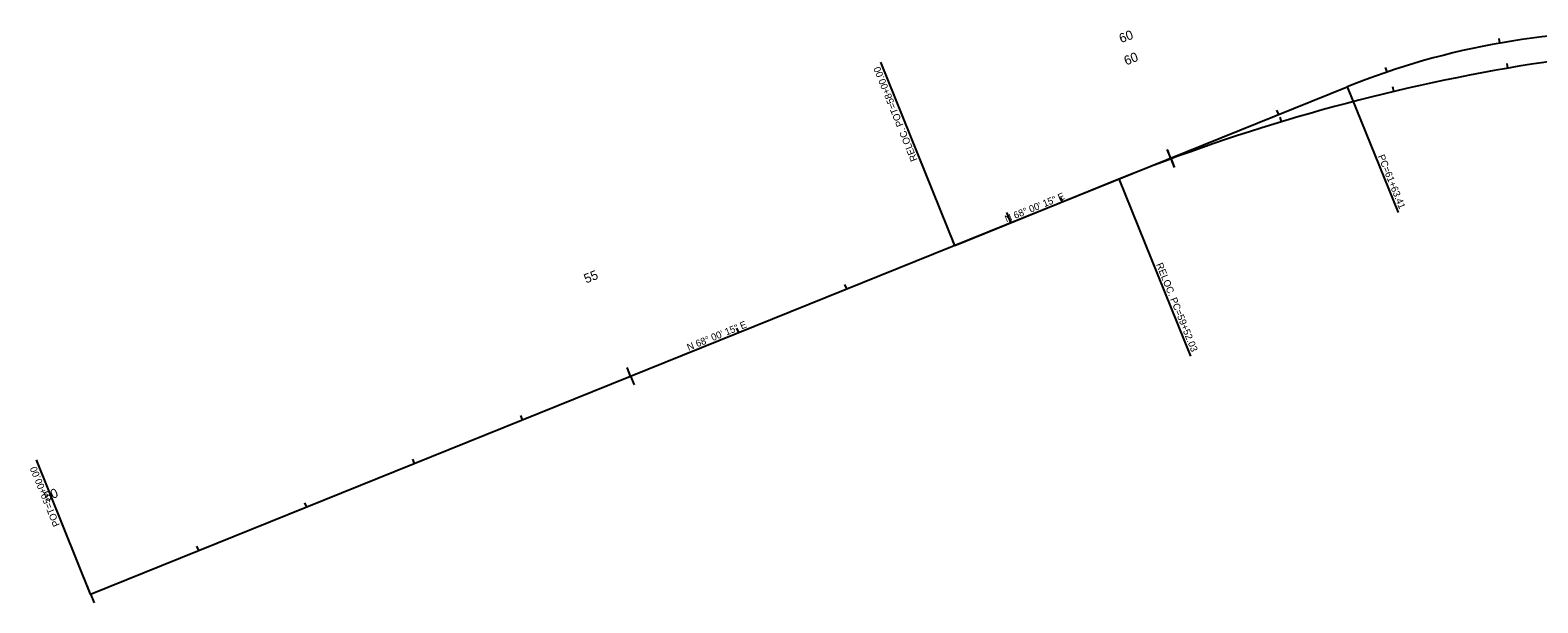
# Model space of a CAD drawing. Extents: x 1966719 to 1969284, y 1117441 to 1118086.
# Drawn here: x 1966719 to 1968013, y 1117441 to 1117933 of the extents above; entities that cross this region are included whole.
import ezdxf

# ---------------------------------------------------------------- set-up
doc = ezdxf.new("R2010")
doc.units = 0
for name, color, linetype in [('Level 1', 7, 'Continuous'), ('Level 19', 7, 'Continuous'), ('Level 21', 7, 'Continuous'), ('Level 39', 7, 'Continuous')]:
    doc.layers.add(name, color=color, linetype=linetype)

msp = doc.modelspace()

# ---------------------------------------------------------------- linework, layer by layer
at = {"layer": 'Level 1'}
for p, q in [((1967980.5, 1117921.5), (1967979.8, 1117925.4)), ((1967883.8, 1117896.6), (1967882.5, 1117900.4)), ((1966770.7, 1117448.1), (1967849.5, 1117883.9)), ((1967849.5, 1117883.9), (1967893.1, 1117775.9)), ((1967790.7, 1117860.1), (1967789.2, 1117863.8)), ((1967698, 1117822.7), (1967695, 1117830.1)), ((1967698, 1117822.7), (1967700.9, 1117815.2)), ((1967605.2, 1117785.2), (1967603.7, 1117788.9)), ((1967512.5, 1117747.7), (1967511, 1117751.5)), ((1967419.8, 1117710.3), (1967418.3, 1117714)), ((1967327.1, 1117672.8), (1967325.6, 1117676.5)), ((1967234.3, 1117635.4), (1967231.3, 1117642.8)), ((1967234.3, 1117635.4), (1967237.3, 1117628)), ((1967141.6, 1117597.9), (1967140.1, 1117601.6)), ((1966770.7, 1117448.1), (1966724.2, 1117563.4)), ((1967048.9, 1117560.5), (1967047.4, 1117564.2)), ((1966956.2, 1117523), (1966954.7, 1117526.7)), ((1966863.5, 1117485.6), (1966862, 1117489.3)), ((1966770.7, 1117448.1), (1966767.7, 1117455.5)), ((1966770.7, 1117448.1), (1966773.7, 1117440.7))]:
    msp.add_line(p, q, dxfattribs=at)
msp.add_arc((1968094.4, 1117277.5), 653.9, 87.7266, 111.9958, dxfattribs=at)
at = {"layer": 'Level 19'}
for p, q in [((1967987.5, 1117899.9), (1967986.8, 1117903.8)), ((1967889.5, 1117879.8), (1967888.6, 1117883.7)), ((1967793, 1117853.8), (1967791.8, 1117857.7)), ((1967698.2, 1117822), (1967695.4, 1117829.5)), ((1967698.2, 1117822), (1967701, 1117814.5)), ((1967512.5, 1117747.7), (1967653.5, 1117804.7)), ((1967605.2, 1117785.2), (1967603.7, 1117788.9)), ((1967560.8, 1117767.2), (1967557.3, 1117775.8)), ((1967512.5, 1117747.7), (1967511, 1117751.5))]:
    msp.add_line(p, q, dxfattribs=at)
msp.add_arc((1968266.6, 1116286.8), 1637, 87.7266, 111.9958, dxfattribs=at)
at = {"layer": 'Level 39'}
for p, q in [((1967512.5, 1117747.7), (1967449, 1117905)), ((1967653.5, 1117804.7), (1967714.9, 1117652.6))]:
    msp.add_line(p, q, dxfattribs=at)

# ---------------------------------------------------------------- texts
at = {"layer": 'Level 1'}
for s, rotation, p in [('PC=61+63.41', 291.9958, (1967875.7, 1117824.3)), ('POT=50+00.00', 111.9958, (1966744.5, 1117507.6))]:
    msp.add_text(s, height=6, rotation=rotation, dxfattribs=at).set_placement(p)
at = {"layer": 'Level 19'}
msp.add_text('60', height=8, rotation=20.3169, dxfattribs=at).set_placement((1967655.4, 1117921.3))
at = {"layer": 'Level 21'}
for s, height, p in [('60', 8, (1967659.8, 1117902.1)), ('55', 8, (1967196.2, 1117714.9)), ('N 68%%d 00\' 15" E', 6, (1967284.1, 1117657.1)), ('50', 8, (1966732.6, 1117527.6))]:
    msp.add_text(s, height=height, rotation=21.9958, dxfattribs=at).set_placement(p)
at = {"layer": 'Level 39'}
for s, rotation, p in [('RELOC. POT=58+00.00', 111.9958, (1967480.7, 1117821.2)), ('N 68%%d 00\' 15" E', 21.9958, (1967557, 1117767.3)), ('RELOC. PC=59+52.03', 291.9958, (1967685.3, 1117731.3))]:
    msp.add_text(s, height=6, rotation=rotation, dxfattribs=at).set_placement(p)

doc.saveas('drawing.dxf')
